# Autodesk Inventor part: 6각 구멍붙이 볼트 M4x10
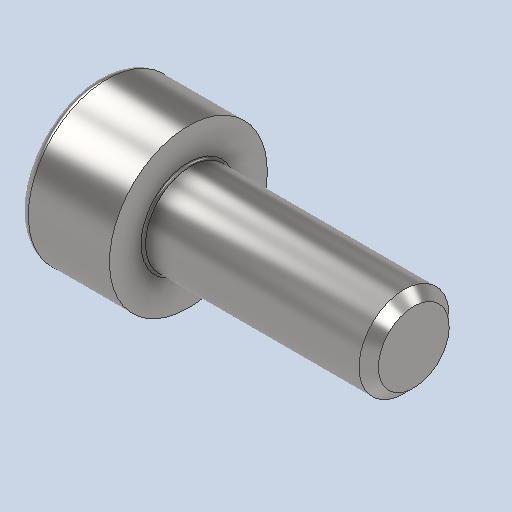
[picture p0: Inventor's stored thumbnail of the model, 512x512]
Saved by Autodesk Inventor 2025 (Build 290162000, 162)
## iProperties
Created: 2026-01
Part Number: 6각 구멍붙이 볼트 M4x10
Material: 강철, 연강
Description: 6각머리 태핑 나사
Document SubType Name: Modeling
Designer: KDI
Density: 7.85 g/cm^3
Appearance: 기본값
Author: jhkim
Sending System: Autodesk Inventor 2026
Preprocessor: ST-DEVELOPER v20.1
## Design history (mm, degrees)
feature "Solid1"
node "솔리드1"
